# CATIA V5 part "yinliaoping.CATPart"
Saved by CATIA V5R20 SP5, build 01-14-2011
Part number: 饮料瓶
Material "Brown Onyx": density 25000 kg/m3, Young's modulus 6e+10 Pa, Poisson ratio 0.27, thermal expansion 7e-06 1/K
Material "Sand": density 1600 kg/m3
Bounding box of the stored display mesh (mm): x -25 to 25.5, y -25 to 25, z 0 to 110
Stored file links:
  C:\000\CAD\yinliaoping.CATPart
  C:\Program Files\Dassault Systemes\B20\intel_a\startup\materials\Catalog.CATMaterial
  C:\Program Files\Dassault Systemes\B20\intel_a\startup\materials\blue_fabric_01.jpg
  C:\Program Files\Dassault Systemes\B20\intel_a\startup\materials\blue_env_512x512.jpg
  C:\Program Files\Dassault Systemes\B20\intel_a\startup\materials\summer_sky.jpg
  C:\Program Files\Dassault Systemes\B20\intel_a\startup\materials\DS_star.jpg
  C:\Program Files\Dassault Systemes\B20\intel_a\startup\materials\brown_onyx.jpg
  C:\Program Files\Dassault Systemes\B20\intel_a\startup\materials\sand.jpg
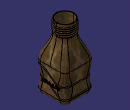
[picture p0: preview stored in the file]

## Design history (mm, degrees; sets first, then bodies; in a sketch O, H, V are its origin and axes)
Set1, material "Sand"
  Sketch1 on xy-plane, origin (0, 0, 0), H (1, 0, 0), V (0, 1, 0)
    line L1 (25, 25) -> (25, -25)
    line L2 (25, -25) -> (-25, -25)
    line L3 (-25, -25) -> (-25, 25)
    line L4 (-25, 25) -> (25, 25)
    length L4 = 50
    length L1 = 50
    vertical: L1 V, L3 V
    horizontal: L2 H, L4 H
    equidistance: L1 L3 O, L2 L4 O
  Sketch2 on face of Pad1 from Sketch1.L1, origin (25, 0, 0), H (0, 1, 0), V (0, 0, 1)
    spline S1 through (-39.2674, 10.6907) (-2.6911, 24.4351) (14.1903, 12.0932) (46.5462, 30.606)
  Extrude1: Element1 Sketch2, Lim1 55, Lim2 55
  MultiSel1: CommonCtxFeats ({extract ExtractElem face of Pad1 from Sketch1.L4}; {extract ExtractElem face of Fillet1}; {extract ExtractElem face of Pad1 from Sketch1.L3}; {extract ExtractElem face of Fillet1}; {extract ExtractElem face of Pad1 from Sketch1.L2}; {extract ExtractElem face of Fillet1}; {extract ExtractElem face of Pad1 from Sketch1.L1}; {extract ExtractElem face of Fillet1})
  Sketch3 on face of Pad1 from Sketch1.L1, origin (25, 0, 0), H (0, 1, 0), V (0, 0, 1)
    spline S1 through (-39.2939, 30.6709) (-12.9173, 43.9604) (13.4593, 28.1262) (38.1341, 41.1328)
  Extrude2: Element1 Sketch3, Lim1 55, Lim2 55
  MultiSel2: CommonCtxFeats ({extract ExtractElem face of Pad1 from Sketch1.L1}; {extract ExtractElem face of Fillet1}; {extract ExtractElem face of Pad1 from Sketch1.L4}; {extract ExtractElem face of Fillet1}; {extract ExtractElem face of Pad1 from Sketch1.L3}; {extract ExtractElem face of Fillet1}; {extract ExtractElem face of Pad1 from Sketch1.L2}; {extract ExtractElem face of Fillet1})
  Join1: Elements ({intersect ToIntersect1 {extract ExtractElem face of Pad1 from Sketch1.L4}, ToIntersect2 Extrude1}; {intersect ToIntersect1 {extract ExtractElem face of Fillet1}, ToIntersect2 Extrude1}; {intersect ToIntersect1 {extract ExtractElem face of Pad1 from Sketch1.L3}, ToIntersect2 Extrude1}; {intersect ToIntersect1 {extract ExtractElem face of Fillet1}, ToIntersect2 Extrude1}; {intersect ToIntersect1 {extract ExtractElem face of Pad1 from Sketch1.L2}, ToIntersect2 Extrude1}; {intersect ToIntersect1 {extract ExtractElem face of Fillet1}, ToIntersect2 Extrude1}; {intersect ToIntersect1 {extract ExtractElem face of Pad1 from Sketch1.L1}, ToIntersect2 Extrude1}; {intersect ToIntersect1 {extract ExtractElem face of Fillet1}, ToIntersect2 Extrude1})
  Join2: Elements ({intersect ToIntersect1 {extract ExtractElem face of Pad1 from Sketch1.L4}, ToIntersect2 Extrude1}; {intersect ToIntersect1 {extract ExtractElem face of Fillet1}, ToIntersect2 Extrude1}; {intersect ToIntersect1 {extract ExtractElem face of Pad1 from Sketch1.L3}, ToIntersect2 Extrude1}; {intersect ToIntersect1 {extract ExtractElem face of Fillet1}, ToIntersect2 Extrude1}; {intersect ToIntersect1 {extract ExtractElem face of Pad1 from Sketch1.L2}, ToIntersect2 Extrude1}; {intersect ToIntersect1 {extract ExtractElem face of Fillet1}, ToIntersect2 Extrude1}; {intersect ToIntersect1 {extract ExtractElem face of Pad1 from Sketch1.L1}, ToIntersect2 Extrude1}; {intersect ToIntersect1 {extract ExtractElem face of Fillet1}, ToIntersect2 Extrude1})
  Plane1: type Normal, Curve Join2, RefPoint vertex [face of MultiSel1 | face of MultiSel1]
  Circle1: type CtrRad, Start 0, End 180, Center vertex [face of MultiSel1 | face of MultiSel1], Support Plane1, Radius 1, FirstDirection (-1, 0, 0)
Body1 (main body), material "Brown Onyx"
  Pad1: profile Sketch1, direction (0, 0, 1), length 50
  Fillet1: on edge [face of Pad1 from Sketch1.L3 | face of Pad1 from Sketch1.L4]; edge [face of Pad1 from Sketch1.L4 | face of Pad1 from Sketch1.L1]; edge [face of Pad1 from Sketch1.L1 | face of Pad1 from Sketch1.L2]; edge [face of Pad1 from Sketch1.L2 | face of Pad1 from Sketch1.L3]
  Fillet2: radius 8, on edge [start face of Pad1 | face of Pad1 from Sketch1.L3]
  Plane2: type Offset, RefPlane end face of Pad1, Offset 40, reversed
  Sketch4 on Plane2, origin (0, 0, 90), H (1, 0, 0), V (0, -1, 0)
    circle A1 centre (0, 0) radius 15
    point P1 (15, 0)
    radius A1 = 15
    coincidence: A1 P1, P1 H
  Pad2: profile Sketch4, direction (0, 0, 1), length 20
  Sketch5 on end face of Pad1, origin (0, 0, 50), H (1, 0, 0), V (0, 1, 0)
    point P1 (25, 0)
    distance P1 V = 25
    coincidence: P1 H
  Sketch6 on start face of Pad2, origin (0, 0, 90), H (1, 0, 0), V (0, -1, 0)
    point P1 (15, 0)
    distance P1 V = 15
    coincidence: P1 H
  Loft1: solid, Sections ({boundary Boundary {extract ExtractElem start face of Pad2}}; {boundary Boundary {extract ExtractElem end face of Pad1}}), StartFace start face of Pad2, EndFace end face of Pad1
  Slot1: profile Circle1, centre curve Join2
  Join3: Elements ({intersect ToIntersect1 {extract ExtractElem face of Pad1 from Sketch1.L1}, ToIntersect2 Extrude2}; {intersect ToIntersect1 {extract ExtractElem face of Fillet1}, ToIntersect2 Extrude2}; {intersect ToIntersect1 {extract ExtractElem face of Pad1 from Sketch1.L4}, ToIntersect2 Extrude2}; {intersect ToIntersect1 {extract ExtractElem face of Fillet1}, ToIntersect2 Extrude2}; {intersect ToIntersect1 {extract ExtractElem face of Pad1 from Sketch1.L3}, ToIntersect2 Extrude2}; {intersect ToIntersect1 {extract ExtractElem face of Fillet1}, ToIntersect2 Extrude2}; {intersect ToIntersect1 {extract ExtractElem face of Pad1 from Sketch1.L2}, ToIntersect2 Extrude2}; {intersect ToIntersect1 {extract ExtractElem face of Fillet1}, ToIntersect2 Extrude2})
  Plane3: type Normal, Curve Join3, RefPoint vertex [face of MultiSel2 | face of MultiSel2]
  Circle2: type CtrRad, Start 0, End 180, Center vertex [face of MultiSel2 | face of MultiSel2], Support Plane3, Radius 1, FirstDirection (1, 0, 0)
  Slot2: profile Circle2, centre curve Join3
  Shell1: ExtOffset 0, Face end face of Pad2, IntOffset 1
  Plane4: type Offset, RefPlane Plane2, Offset 2, reversed
  Sketch7 on Plane4, origin (0, 0, 92), H (1, 0, 0), V (0, -1, 0)
    point P1 (15, 0)
    distance P1 O = 15
    coincidence: P1 H
  Helix1: Direction Z axis, RefPoint Sketch7, Pitch 3, Height 15, TaperAngle 0
  Point1: type OnCurve, Support Helix1, RefPoint Sketch7, Length -5
  Line1: type PtDir, RefPoint Sketch7, Direction (1, 0, 0), Start 0, End -10
  Connect1: Curve1 Line1, Point1 vertex of Line1, Tension1 1, Curve2 Helix1, Point2 Point1, Tension2 1
  Point2: type OnCurve, Support Connect1, RefPoint vertex of Helix1, Length -5
  Line2: type PtDir, RefPoint vertex of Helix1, Direction (1, 0, 0), Start 0, End -10
  Connect2: Curve1 Line2, Point1 vertex of Line2, Tension1 1, Curve2 Connect1, Point2 Point2, Tension2 1
  Plane5: type Normal, Curve Connect2, RefPoint vertex of Connect2
  Plane6: type Normal, Curve Connect2, RefPoint vertex of Connect1
  Circle3: type CtrRad, Start 0, End 180, Center vertex of Connect2, Support Plane5, Radius 1, FirstDirection (0, 1, 0)
  Circle4: type CtrRad, Start 0, End 180, Center vertex of Connect1, Support Plane6, Radius 1, FirstDirection (0, -1, 0)
  Rib1: profile Circle3, centre curve Connect2
  Body2
    Sketch8 on Plane2, origin (0, 0, 90), H (1, 0, 0), V (0, -1, 0)
      circle A1 centre (0, 0) radius 14
      radius A1 = 14
    Pad3: profile Sketch8, direction (0, 0, 1), length 20
  Remove1: tool Body2
Body3
  Sketch9 on face of Pad1 from Sketch1.L1, origin (25, 0, 0), H (0, 1, 0), V (0, 0, 1)
    polyline C1
    polyline C2
    polyline C3
    polyline C4
    polyline C5
    polyline C6
    polyline C7
    polyline C8
    polyline C9
    polyline C10
    polyline C11
  Pad4: profile Sketch9, direction (1, 0, 0), length 0.5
